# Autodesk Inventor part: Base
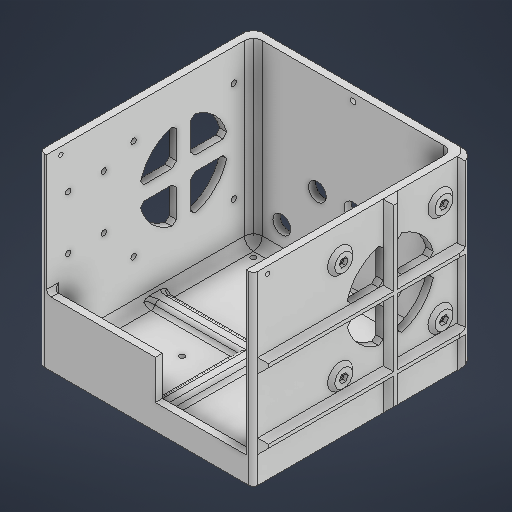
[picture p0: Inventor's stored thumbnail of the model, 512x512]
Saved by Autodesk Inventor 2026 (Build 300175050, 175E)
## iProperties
Created: 2023-12
Part Number: Base
Material: Generic
Document SubType Name: Modeling
Designer: Andrew
Density: 1 g/cm^3
Appearance: Default
Author: Andrew
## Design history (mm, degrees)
sketch "Sketch1"
  geometry: L1 (76.2, 76.2)-(-76.2, 76.2); L2 (-76.2, 76.2)-(-76.2, -76.2); L3 (-76.2, -76.2)-(76.2, -76.2); L4 (76.2, -76.2)-(76.2, 76.2); 1 further point
  constraints: 8 end point, 2 parallel, 1 horizontal, 1 perpendicular
  dimensions: "d1" = 152.4 distance between parallel lines of L2 L4; "d2" = 152.4 distance between parallel lines of L3 L1 (= d1); "d3" = 76.2 distance from line of point (0, 0) L4 (= 0.5 x d2); "d4" = 76.2 distance from line of L3 point (0, 0) (= 0.5 x d1)
extrude "Extrusion1" new body sketch "Sketch1" distance "d5" = 5.08; taper "d6" = 0 deg
sketch "Sketch2"
  geometry: L1 (-71.12, 71.12)-(71.12, 71.12); L2 (71.12, 71.12)-(71.12, -71.12); L3 (-71.12, -58.42)-(-71.12, 71.12); L4 (76.2, -76.2)-(76.2, 76.2) reference; L5 (76.2, 76.2)-(-76.2, 76.2) reference; L6 (-76.2, 76.2)-(-76.2, -76.2) reference; L7 (-76.2, -76.2)-(76.2, -76.2) reference; L8 (-71.12, -58.42)-(-71.12, -76.2); L9 (71.12, -71.12)-(71.12, -76.2); 1 further point
  constraints: 10 end point, 3 perpendicular, 2 point on line, 1 horizontal, 1 parallel
  dimensions: "d7" = 5.08 distance between parallel lines of L5 L1; "d8" = 5.08 distance between parallel lines of L6 L3 (= d7); "d9" = 5.08 distance between parallel lines of L4 L2 (= d7)
extrude "Extrusion2" join sketch "Sketch2" distance "d11" = 127; taper "d12" = 0 deg
sketch "Sketch3"
  geometry: L1 (152.4, 0)-(152.4, 132.08) reference; L2 (0, 0)-(0, 132.08) reference; L3 (0, 0)-(152.4, 0) reference; C1 r 6.35 at (101.6, 58.42); C2 r 6.35 at (127, 25.4); C3 r 6.35 at (76.2, 58.42); 1 further point
  constraints: 3 centre point, 1 horizontal alignment
  dimensions: "d13" = 50.8 distance from line of C1.centre L1 (derived); "d14" = 152.4 distance between parallel lines of L2 L1 (derived); "d15" = 58.42 distance from line of L3 C1.centre; "d16" = 12.7 diameter of C1; "d41" = 12.7 diameter of C2 (= d16); "d42" = 12.7 diameter of C3 (= d16); "d43" = 25.4 distance of C1.centre C3.centre; "d176" = 25.4 horizontal distance of C2.centre C1.centre; "d177" = 25.4 distance from line of L3 C2.centre
extrude "Extrusion3" cut sketch "Sketch3" stored distance "d17" = 127; taper "d18" = 0 deg
sketch "Sketch4"
  geometry: L1 (152.4, 0)-(152.4, 132.08) reference; L2 (0, 0)-(0, 132.08) reference; L3 (0, 0)-(152.4, 0) reference; C1 r 1.905 at (61.874, 109.576); C2 r 1.905 at (133.35, 109.576); C3 r 1.905 at (61.874, 38.1); C4 r 1.905 at (133.35, 38.1); 1 further point
  constraints: 4 centre point, 2 horizontal alignment, 2 vertical alignment
  dimensions: "d19" = 71.4756 distance of C2.centre C1.centre; "d20" = 71.4756 distance of C4.centre C2.centre (= d19); "d21" = 3.81 diameter of C2; "d22" = 3.81 diameter of C4 (= d21); "d23" = 3.81 diameter of C3 (= d21); "d24" = 3.81 diameter of C1 (= d21); "d25" = 152.4 distance between parallel lines of L1 L2 (derived); "d26" = 19.05 distance from line of L1 C2.centre; "d27" = 38.1 distance from line of L3 C4.centre
extrude "Extrusion4" cut sketch "Sketch4" extent not by distance; stored distance "d28" = 0; taper "d29" = 0 deg
sketch "Sketch5"
  geometry: C1 r 31.75 at (97.612, 73.838); C2 r 1.905 at (133.35, 109.576) reference; C3 r 1.905 at (61.874, 109.576) reference; C4 r 1.905 at (133.35, 38.1) reference; 1 further point
  constraints: 1 centre point
  dimensions: "d30" = 71.4756 distance of C2.centre C3.centre (derived); "d31" = 71.4756 distance of C4.centre C2.centre (derived); "d32" = 35.7378 horizontal distance of C2.centre C1.centre (= 0.5 x d30); "d33" = 35.7378 horizontal distance of C4.centre C1.centre (= 0.5 x d31); "d34" = 63.5 diameter of C1
extrude "Extrusion5" cut sketch "Sketch5" extent not by distance; stored distance "d35" = 0; taper "d36" = 0 deg
sketch "Sketch6"
  geometry: L1 (-71.12, -76.2)-(71.12, -76.2) reference; L2 (71.12, -76.2)-(71.12, 71.12) reference; L3 (-71.12, -76.2)-(71.12, -76.2); L4 (71.12, -76.2)-(71.12, -71.12); L5 (71.12, -71.12)-(-71.12, -71.12); L6 (-71.12, -71.12)-(-71.12, -76.2); 1 further point
  constraints: 8 end point, 2 parallel, 1 horizontal, 1 perpendicular, 1 point on line
  dimensions: "d38" = 5.08 distance between parallel lines of L1 L5
extrude "Extrusion6" join sketch "Sketch6" distance "d39" = 12.7; taper "d40" = 0 deg
fillet "Fillet1" dims "d37" = 3.175
fillet "Fillet5" dims "d220" = 6.35
sketch "Sketch7"
  geometry: L1 (149.225, 0)-(149.225, 132.08) reference; L2 (137.795, 5.08)-(8.255, 5.08) reference; C1 r 1.905 at (108.585, 101.6); C2 r 1.905 at (133.985, 101.6); C3 r 1.905 at (108.585, 63.5); C4 r 1.905 at (133.985, 63.5); 2 further points
  constraints: 4 centre point, 2 horizontal alignment, 2 vertical alignment
  dimensions: "d45" = 3.81 diameter of C1; "d46" = 3.81 diameter of C2 (= d45); "d47" = 3.81 diameter of C4 (= d45); "d48" = 3.81 diameter of C3 (= d45); "d49" = 38.1 distance of C4.centre C2.centre; "d50" = 25.4 distance of C4.centre C3.centre; "d51" = 15.24 distance from line of L1 C2.centre; "d221" = 58.42 distance from line of L2 C3.centre
extrude "Extrusion7" cut sketch "Sketch7" distance "d53" = 25.4; taper "d54" = 0 deg
sketch "Sketch8"
  geometry: L1 (-76.2, 73.025)-(-76.2, -73.025) reference; L2 (76.2, -73.025)-(76.2, 73.025) reference; L3 (73.025, 76.2)-(-73.025, 76.2) reference; L4 (-73.025, -76.2)-(73.025, -76.2) reference; C1 r 1.905 at (-25.4, -25.4); C2 r 1.905 at (-25.4, 25.4); C3 r 1.905 at (25.4, 25.4); C4 r 1.905 at (25.4, -25.4); 1 further point
  constraints: 4 centre point, 2 horizontal alignment, 2 vertical alignment
  dimensions: "d55" = 3.81 diameter of C1; "d56" = 3.81 diameter of C2 (= d55); "d57" = 3.81 diameter of C3 (= d55); "d58" = 3.81 diameter of C4 (= d55); "d59" = 50.8 distance of C2.centre C1.centre; "d60" = 50.8 distance of C4.centre C1.centre; "d61" = 152.4 distance between parallel lines of L1 L2 (derived); "d62" = 152.4 distance between parallel lines of L3 L4 (derived); "d63" = 50.8 distance from line of L1 C1.centre (= -0.5 x d60 + 0.5 x d61); "d64" = 50.8 distance from line of L4 C1.centre (= -0.5 x d60 + 0.5 x d62)
extrude "Extrusion8" cut sketch "Sketch8" distance "d65" = 25.4; taper "d66" = 0 deg
sketch "Sketch10"
  geometry: L1 (-76.2, -73.025)-(-76.2, 73.025) reference; L2 (-73.025, 76.2)-(73.025, 76.2) reference; L3 (76.2, 73.025)-(76.2, -73.025) reference; L4 (73.025, -76.2)-(-73.025, -76.2) reference; C1 r 1.905 at (-60.96, 60.96); C2 r 1.905 at (60.96, 60.96); C3 r 1.905 at (60.96, -60.96); C4 r 1.905 at (-60.96, -60.96); 1 further point
  constraints: 4 centre point, 2 vertical alignment, 1 horizontal alignment
  dimensions: "d67" = 3.81 diameter of C1; "d68" = 3.81 diameter of C2 (= d67); "d69" = 3.81 diameter of C3 (= d68); "d70" = 3.81 diameter of C4 (= d69); "d71" = 15.24 distance from line of L1 C1.centre; "d72" = 15.24 distance from line of L2 C1.centre; "d73" = 15.24 distance from line of L2 C2.centre (= d72); "d74" = 15.24 distance from line of L3 C2.centre (= d71); "d75" = 15.24 distance from line of L4 C3.centre (= d73)
extrude "Extrusion9" cut sketch "Sketch10" distance "d76" = 25.4; taper "d77" = 0 deg
sketch "Sketch12"
  geometry: L1 (0, 132.08)-(146.05, 132.08) reference; L2 (149.225, 0)-(149.225, 132.08) reference; C1 r 1.524 at (139.065, 127); 1 further point
  constraints: 1 centre point
  dimensions: "d78" = 3.048 diameter of C1; "d79" = 5.08 distance from line of L1 C1.centre; "d80" = 10.16 distance from line of L2 C1.centre
extrude "Extrusion10" cut sketch "Sketch12" extent not by distance; stored distance "d81" = 0; taper "d82" = 0 deg
sketch "Sketch19"
  geometry: C1 r 1.905 at (87.351, 109.576) reference; C2 r 6.35 at (87.351, 109.576); C3 r 1.905 at (87.351, 38.1) reference; C4 r 6.35 at (87.351, 38.1); C5 r 1.905 at (15.875, 109.576) reference; C6 r 6.35 at (15.875, 109.576); C7 r 1.905 at (15.875, 38.1) reference; C8 r 6.35 at (15.875, 38.1); 1 further point
  constraints: 4 centre point, 4 coincident
  dimensions: "d127" = 12.7 diameter of C6; "d128" = 12.7 diameter of C8 (= d127); "d129" = 12.7 diameter of C2 (= d127); "d130" = 12.7 diameter of C4 (= d127)
extrude "Extrusion16" join sketch "Sketch19" distance "d131" = 2.54; taper "d132" = 0 deg
chamfer "Chamfer2" distance "d133" = 2.54; stored, may be unused: second distance "d134" = 3.175, angle "d135" = 45 deg
sketch "Sketch13"
  geometry: L1 (17.459, 112.319)-(19.043, 109.576); L2 (19.043, 109.576)-(17.459, 106.832); L3 (17.459, 106.832)-(14.291, 106.832); L4 (14.291, 106.832)-(12.707, 109.576); L5 (12.707, 109.576)-(14.291, 112.319); L6 (14.291, 112.319)-(17.459, 112.319); L7 (88.934, 112.319)-(90.518, 109.576); L8 (90.518, 109.576)-(88.934, 106.832); L9 (88.934, 106.832)-(85.767, 106.832); L10 (85.767, 106.832)-(84.183, 109.576); L11 (84.183, 109.576)-(85.767, 112.319); L12 (85.767, 112.319)-(88.934, 112.319); L13 (88.934, 40.843)-(90.518, 38.1); L14 (90.518, 38.1)-(88.934, 35.357); L15 (88.934, 35.357)-(85.767, 35.357); L16 (85.767, 35.357)-(84.183, 38.1); L17 (84.183, 38.1)-(85.767, 40.843); L18 (85.767, 40.843)-(88.934, 40.843); L19 (17.459, 40.843)-(19.043, 38.1); L20 (19.043, 38.1)-(17.459, 35.357); L21 (17.459, 35.357)-(14.291, 35.357); L22 (14.291, 35.357)-(12.707, 38.1); L23 (12.707, 38.1)-(14.291, 40.843); L24 (14.291, 40.843)-(17.459, 40.843); C1 r 1.905 at (15.875, 109.576) reference; C2 r 1.905 at (87.351, 109.576) reference; C3 r 1.905 at (87.351, 38.1) reference; C4 r 1.905 at (15.875, 38.1) reference; 5 further points
  constraints: 48 end point, 4 coincident, 4 horizontal, 52 other
  dimensions: "d83" = 5.4864 distance between parallel lines of L3 L6; "d84" = 5.4864 distance between parallel lines of L9 L12 (= d83); "d85" = 5.4864 distance between parallel lines of L21 L24 (= d83); "d86" = 5.4864 distance between parallel lines of L15 L18 (= d83)
extrude "Extrusion11" cut sketch "Sketch13" distance "d91" = 2.54; taper "d92" = 0 deg
sketch "Sketch20"
  geometry: C1 r 1.905 at (130.175, 38.1) reference; C2 r 6.35 at (130.175, 38.1); C3 r 1.905 at (58.699, 38.1) reference; C4 r 6.35 at (58.699, 38.1); C5 r 1.905 at (130.175, 109.576) reference; C6 r 6.35 at (130.175, 109.576); C7 r 1.905 at (58.699, 109.576) reference; C8 r 6.35 at (58.699, 109.576); 1 further point
  constraints: 4 centre point, 4 coincident
  dimensions: "d136" = 12.7 diameter of C6; "d137" = 12.7 diameter of C8 (= d136); "d138" = 12.7 diameter of C2 (= d136); "d139" = 12.7 diameter of C4 (= d136)
extrude "Extrusion17" join sketch "Sketch20" distance "d140" = 2.54; taper "d141" = 0 deg
chamfer "Chamfer3" distance "d142" = 2.54; stored, may be unused: second distance "d143" = 3.175, angle "d144" = 45 deg
sketch "Sketch14"
  geometry: L1 (60.283, 112.319)-(61.867, 109.576); L2 (61.867, 109.576)-(60.283, 106.832); L3 (60.283, 106.832)-(57.116, 106.832); L4 (57.116, 106.832)-(55.532, 109.576); L5 (55.532, 109.576)-(57.116, 112.319); L6 (57.116, 112.319)-(60.283, 112.319); L7 (131.759, 112.319)-(133.343, 109.576); L8 (133.343, 109.576)-(131.759, 106.832); L9 (131.759, 106.832)-(128.591, 106.832); L10 (128.591, 106.832)-(127.007, 109.576); L11 (127.007, 109.576)-(128.591, 112.319); L12 (128.591, 112.319)-(131.759, 112.319); L13 (131.759, 40.843)-(133.343, 38.1); L14 (133.343, 38.1)-(131.759, 35.357); L15 (131.759, 35.357)-(128.591, 35.357); L16 (128.591, 35.357)-(127.007, 38.1); L17 (127.007, 38.1)-(128.591, 40.843); L18 (128.591, 40.843)-(131.759, 40.843); L19 (60.283, 40.843)-(61.867, 38.1); L20 (61.867, 38.1)-(60.283, 35.357); L21 (60.283, 35.357)-(57.116, 35.357); L22 (57.116, 35.357)-(55.532, 38.1); L23 (55.532, 38.1)-(57.116, 40.843); L24 (57.116, 40.843)-(60.283, 40.843); C1 r 1.905 at (58.699, 109.576) reference; C2 r 1.905 at (130.175, 109.576) reference; C3 r 1.905 at (130.175, 38.1) reference; C4 r 1.905 at (58.699, 38.1) reference; 14 further points
  constraints: 48 end point, 8 midpoint, 4 coincident, 4 horizontal, 52 other
  dimensions: "d93" = 5.4864 distance of point (130.175, 106.832) point (130.175, 112.319); "d94" = 5.4864 distance of point (58.699, 106.832) point (58.699, 112.319) (= d93); "d95" = 5.4864 distance of point (130.175, 35.357) point (130.175, 40.843) (= d93); "d96" = 5.4864 distance of point (58.699, 35.357) point (58.699, 40.843) (= d93)
extrude "Extrusion12" cut sketch "Sketch14" distance "d101" = 2.54; taper "d102" = 0 deg
sketch "Sketch15"
  geometry: L1 (0, 132.08)-(146.05, 132.08) reference; L2 (-3.175, 132.08)-(-3.175, 0) reference; L3 (149.225, 0)-(149.225, 132.08) reference; C1 r 1.905 at (73.025, 127); 1 further point
  constraints: 1 centre point
  dimensions: "d103" = 3.81 diameter of C1; "d104" = 5.08 distance from line of L1 C1.centre; "d257" = 152.4 distance between parallel lines of L3 L2 (derived); "d258" = 76.2 distance from line of C1.centre L2 (derived)
extrude "Extrusion13" cut sketch "Sketch15" extent not by distance; stored distance "d106" = 0; taper "d107" = 0 deg
sketch "Sketch23"
  geometry: L1 (-71.12, -76.2)-(71.12, -76.2) reference; L2 (71.12, -67.945)-(71.12, -76.2) reference; L3 (67.945, -71.12)-(-67.945, -71.12) reference; L4 (-71.12, -76.2)-(-71.12, -67.945) reference; L5 (6.35, -71.12)-(6.35, -76.2); A1 r 3.175 centre (67.945, -67.945) between (67.945, -71.12) and (71.12, -67.945) reference; A2 r 3.175 centre (-67.945, -67.945) between (-71.12, -67.945) and (-67.945, -71.12) reference; 1 further point
  constraints: 2 end point, 2 point on line, 1 perpendicular
  dimensions: "d158" = 77.47 distance between parallel lines of L5 L4
extrude "Extrusion19" join sketch "Sketch23" distance "d159" = 27.94; taper "d160" = 0 deg
fillet "Fillet2" dims "d161" = 3.175
sketch "Sketch24"
  geometry: L1 (-71.12, 5.08)-(71.12, 5.08); L2 (71.12, 5.08)-(71.12, -5.08); L3 (71.12, -5.08)-(-71.12, -5.08); L4 (-71.12, -5.08)-(-71.12, 5.08); L5 (-5.08, -71.12)-(5.08, -71.12); L6 (5.08, -71.12)-(5.08, 71.12); L7 (5.08, 71.12)-(-5.08, 71.12); L8 (-5.08, 71.12)-(-5.08, -71.12); L9 (-64.77, -71.12)-(64.77, -71.12) reference; L10 (67.945, 71.12)-(-67.945, 71.12) reference; L11 (-71.12, 67.945)-(-71.12, -67.945) reference; L12 (71.12, -67.945)-(71.12, 67.945) reference; L13 (-71.12, 64.77)-(-71.12, -67.945) reference; L14 (71.12, -67.945)-(71.12, 64.77) reference; L15 (-67.945, -71.12)-(67.945, -71.12) reference; 6 further points
  constraints: 16 end point, 4 parallel, 2 horizontal, 2 perpendicular, 1 midpoint
  dimensions: "d166" = 10.16 distance between parallel lines of L6 L8; "d169" = 5.08 distance from line of point (0, 5.08) L8 (= 0.5 x d166); "d170" = 10.16 distance between parallel lines of L1 L3 (= d166); "d173" = 5.08 distance from line of point (0, 0) L3 (= d169); "d222" = 0 distance between parallel lines of L13 L4; "d223" = 0 distance between parallel lines of L14 L2; "d242" = 0 distance between parallel lines of L15 L5
extrude "Extrusion20" join sketch "Sketch24" distance "d171" = 3.81; taper "d172" = 0 deg
fillet "Fillet3" dims "d174" = 3.175
sketch "Sketch27"
  geometry: L1 (89.357, 112.215)-(99.517, 112.215); L2 (99.517, 112.215)-(99.517, 22.339); L3 (99.517, 22.339)-(89.357, 22.339); L4 (89.357, 22.339)-(89.357, 112.215); L5 (37.71, 78.918)-(139.723, 78.918); L6 (139.723, 78.918)-(139.723, 68.758); L7 (139.723, 68.758)-(37.71, 68.758); L8 (37.71, 68.758)-(37.71, 78.918); C1 r 31.75 at (94.437, 73.838) reference; 13 further points
  constraints: 16 end point, 4 parallel, 2 horizontal, 2 perpendicular
  dimensions: "d195" = 10.16 distance between parallel lines of L7 L5; "d196" = 10.16 distance between parallel lines of L2 L4; "d197" = 5.08 distance from line of C1.centre L7 (derived); "d198" = 5.08 distance from line of C1.centre L4 (derived)
extrude "Extrusion22" join sketch "Sketch27" stored distance "d199" = 3.81; taper "d200" = 0 deg
sketch "Sketch28"
  geometry: L1 (46.533, 115.112)-(56.693, 115.112); L2 (56.693, 115.112)-(56.693, 32.229); L3 (56.693, 32.229)-(46.533, 32.229); L4 (46.533, 32.229)-(46.533, 115.112); L5 (5.07, 78.918)-(94.583, 78.918); L6 (94.583, 78.918)-(94.583, 68.758); L7 (94.583, 68.758)-(5.07, 68.758); L8 (5.07, 68.758)-(5.07, 78.918); L9 (56.693, 78.918)-(82.954, 78.918) reference; L10 (82.954, 68.758)-(56.693, 68.758) reference; L11 (56.693, 68.758)-(56.693, 42.497) reference; L12 (46.533, 42.497)-(46.533, 68.758) reference; A1 r 31.75 centre (51.613, 73.838) between (82.954, 78.918) and (82.954, 68.758) reference; 13 further points
  constraints: 16 end point, 4 collinear, 4 parallel, 2 horizontal, 2 perpendicular
extrude "Extrusion23" join sketch "Sketch28" stored distance "d201" = 25.4; taper "d202" = 0 deg
chamfer "Chamfer6" distance "d203" = 3.175; stored, may be unused: second distance "d204" = 3.175, angle "d205" = 45 deg
sketch "Sketch30"
  geometry: L1 (0, 78.918)-(146.05, 78.918); L2 (146.05, 78.918)-(146.05, 68.758); L3 (146.05, 68.758)-(0, 68.758); L4 (0, 68.758)-(0, 78.918); L5 (122.603, 78.918)-(102.692, 78.918) reference; L6 (102.692, 68.758)-(122.603, 68.758) reference; L7 (146.05, 132.08)-(146.05, 0) reference; L8 (0, 0)-(0, 132.08) reference; L9 (0, 29.21)-(146.05, 29.21); L10 (146.05, 29.21)-(146.05, 19.05); L11 (146.05, 19.05)-(0, 19.05); L12 (0, 19.05)-(0, 29.21); C1 r 8.89 at (130.175, 38.1) reference; 5 further points
  constraints: 16 end point, 6 collinear, 4 parallel, 2 horizontal, 2 perpendicular
  dimensions: "d216" = 10.16 distance between parallel lines of L11 L9; "d217" = 0 distance edge to line of C1 L9
extrude "Extrusion24" join sketch "Sketch30" distance "d206" = 3.81; taper "d207" = 0 deg
sketch "Sketch31"
  geometry: L1 (0, 78.918)-(146.05, 78.918); L2 (146.05, 78.918)-(146.05, 68.758); L3 (146.05, 68.758)-(0, 68.758); L4 (0, 68.758)-(0, 78.918); L5 (43.358, 78.918)-(23.447, 78.918) reference; L6 (23.447, 68.758)-(43.358, 68.758) reference; L7 (0, 0)-(0, 132.08) reference; L8 (146.05, 132.08)-(146.05, 0) reference; L9 (0, 29.21)-(146.05, 29.21); L10 (146.05, 29.21)-(146.05, 19.05); L11 (146.05, 19.05)-(0, 19.05); L12 (0, 19.05)-(0, 29.21); C1 r 8.89 at (87.351, 38.1) reference; 4 further points
  constraints: 16 end point, 6 collinear, 4 parallel, 2 horizontal, 2 perpendicular
  dimensions: "d218" = 10.16 distance between parallel lines of L11 L9; "d219" = 0 distance edge to line of C1 L9
extrude "Extrusion25" join sketch "Sketch31" distance "d211" = 3.81; taper "d212" = 0 deg
sketch "Sketch32"
  geometry: L1 (-8.255, 81.703)-(137.795, 81.703); L2 (137.795, 81.703)-(137.795, 71.543); L3 (137.795, 71.543)-(-8.255, 71.543); L4 (-8.255, 71.543)-(-8.255, 81.703); L5 (-8.255, 37.677)-(137.795, 37.677); L6 (137.795, 37.677)-(137.795, 27.517); L7 (137.795, 27.517)-(-8.255, 27.517); L8 (-8.255, 27.517)-(-8.255, 37.677); L9 (-8.255, -11.43)-(137.795, -11.43) reference; L10 (0, 120.65)-(129.54, 120.65) reference; L11 (135.89, 0)-(135.89, 120.65) reference; L12 (137.795, -11.43)-(137.795, 120.65) reference; L13 (-8.255, 120.65)-(-8.255, -11.43) reference; 3 further points
  constraints: 16 end point, 4 parallel, 2 horizontal, 2 midpoint, 2 perpendicular
  dimensions: "d227" = 10.16 distance between parallel lines of L3 L1; "d228" = 10.16 distance between parallel lines of L7 L5; "d229" = 132.08 distance between parallel lines of L9 L10 (derived); "d230" = 44.02667 distance from line of L10 point (137.795, 76.623) (derived); "d231" = 44.02667 distance from line of L9 point (137.795, 32.597) (derived); "d259" = 0 distance between parallel lines of L12 L2; "d260" = 0 distance between parallel lines of L6 L2; "d261" = 0 distance between parallel lines of L13 L4; "d262" = 0 distance between parallel lines of L13 L8
extrude "Extrusion26" join sketch "Sketch32" distance "d237" = 3.81; taper "d238" = 0 deg
chamfer "Chamfer9" distance "d239" = 3.81; stored, may be unused: second distance "d240" = 3.175, angle "d241" = 45 deg
sketch "Sketch33"
  geometry: L1 (89.357, 0)-(99.517, 0); L2 (99.517, 0)-(99.517, -132.08); L3 (99.517, -132.08)-(89.357, -132.08); L4 (89.357, -132.08)-(89.357, 0); L5 (0, 0)-(146.05, 0) reference; L6 (0, -132.08)-(146.05, -132.08) reference; L7 (89.357, -30.076)-(89.357, -49.987) reference; 1 further point
  constraints: 8 end point, 2 parallel, 1 collinear, 1 horizontal, 1 perpendicular
  dimensions: "d243" = 10.16 distance between parallel lines of L2 L4; "d244" = 0 distance between parallel lines of L5 L1; "d245" = 0 distance between parallel lines of L6 L3
extrude "Extrusion27" join sketch "Sketch33" distance "d246" = 3.81; taper "d247" = 0 deg
chamfer "Chamfer10" distance "d248" = 3.81; stored, may be unused: second distance "d249" = 3.175, angle "d250" = 45 deg
sketch "Sketch34"
  geometry: L1 (46.533, 0)-(56.693, 0); L2 (56.693, 0)-(56.693, -132.08); L3 (56.693, -132.08)-(46.533, -132.08); L4 (46.533, -132.08)-(46.533, 0); L5 (46.533, -30.076)-(46.533, -49.987) reference; L6 (0, 0)-(146.05, 0) reference; L7 (0, -132.08)-(146.05, -132.08) reference; 1 further point
  constraints: 8 end point, 3 collinear, 2 parallel, 1 horizontal, 1 perpendicular
  dimensions: "d251" = 10.16 distance between parallel lines of L2 L4
extrude "Extrusion28" join sketch "Sketch34" distance "d252" = 3.81; taper "d253" = 0 deg
chamfer "Chamfer11" distance "d254" = 3.81; stored, may be unused: second distance "d255" = 3.175, angle "d256" = 45 deg
sketch "Sketch37"
  geometry: L1 (69.215, -80.01)-(73.025, -76.2) reference; L2 (80.01, -69.215)-(76.2, -73.025) reference; L3 (-69.215, -80.01)-(-73.025, -76.2) reference; L4 (-80.01, -69.215)-(-76.2, -73.025) reference; L5 (-69.215, -80.01)-(69.215, -80.01) reference; L6 (-69.215, -80.01)-(-80.01, -80.01); L7 (-80.01, -80.01)-(-80.01, -69.215); L8 (-80.01, -69.215)-(-69.215, -69.215); L9 (-69.215, -69.215)-(-69.215, -80.01); L10 (80.01, -22.682)-(80.01, -69.215) reference; L11 (69.215, -80.01)-(80.01, -80.01); L12 (80.01, -80.01)-(80.01, -69.215); L13 (80.01, -69.215)-(69.215, -69.215); L14 (69.215, -69.215)-(69.215, -80.01); A1 r 3.175 centre (73.025, -73.025) between (73.025, -76.2) and (76.2, -73.025) reference; A2 r 3.175 centre (-73.025, -73.025) between (-76.2, -73.025) and (-73.025, -76.2) reference; 1 further point
  constraints: 16 end point, 4 parallel, 2 horizontal, 2 perpendicular
extrude "Extrusion29" join sketch "Sketch37" stored distance "d264" = 3.81; taper "d265" = 0 deg
fillet "Fillet6" dims "d266" = 12.7
chamfer "Chamfer12" distance "d268" = 3.175; stored, may be unused: second distance "d269" = 3.175, angle "d270" = 45 deg
body "Solid1"
node "Projected Loop1"
node "Projected Loop6"
